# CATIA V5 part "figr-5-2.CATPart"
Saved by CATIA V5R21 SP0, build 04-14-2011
Part number: Part1
Bounding box of the stored display mesh (mm): x -23 to 23, y -104 to 104, z 0 to 68
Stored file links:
  D:\CATIA V5R21 E-RESOURCES\CATIA-V5R21\catia-v5r21-prt\c05-catia-v5r20-prt\catia-v5r21-figr-5-2.CATPart
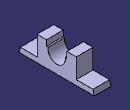
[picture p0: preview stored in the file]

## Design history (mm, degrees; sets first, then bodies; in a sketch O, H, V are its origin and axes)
Sketch1 on yz-plane, origin (0, 0, 0), H (0, 1, 0), V (0, 0, 1)
  line L1 (0, 0) -> (104, 0)
  point P1 (104, 0)
  line L2 (104, 0) -> (100, 14)
  point P2 (100, 14)
  line L3 (100, 14) -> (54, 14)
  point P3 (54, 14)
  line L4 (54, 14) -> (54, 68)
  point P4 (54, 68)
  line L5 (54, 68) -> (28, 68)
  point P5 (28, 68)
  line L6 (28, 68) -> (28, 52)
  point P6 (28, 52)
  line L7 (28, 52) -> (23.6643, 52)
  axis line L8 (0, 0) -> (0, 150)
  point P8 (0, 0)
  construction line L9 through (0, 0) direction (-1, 0)
  construction line L10 through (0, 0) direction (0, 1)
  point P13 (-104, 0)
  point P14 (-100, 14)
  point P15 (-54, 14)
  point P16 (-54, 68)
  point P17 (-28, 68)
  point P18 (-28, 52)
  line L11 (0, 0) -> (-104, 0)
  line L12 (-104, 0) -> (-100, 14)
  line L13 (-100, 14) -> (-54, 14)
  line L14 (-54, 14) -> (-54, 68)
  line L15 (-54, 68) -> (-28, 68)
  line L16 (-28, 68) -> (-28, 52)
  line L17 (-28, 52) -> (-23.6643, 52)
  arc A1 centre (0, 48) radius 24 from (-23.6643, 52) to (23.6643, 52) ccw
  point P19 (0, 48)
  point P20 (13.2665, 68)
  distance P1 P13 = 208
  length L2 V = 14
  length L2 H = 4
  distance L4 L14 = 108
  distance L16 L6 = 56
  distance L1 L5 = 68
  length L6 = 16
  distance P19 L7 = 4
  radius A1 = 24
  horizontal: L1 H, L3 H, L5 H, L7 H
  vertical: L4 V, L6 V, L8 V
  symmetry: O P8 L8, H L9 L8, V L10 L8, P1 P13 L8, P2 P14 L8, P3 P15 L8, P4 P16 L8, P5 P17 L8, P6 P18 L8, L1 L11 L8, L2 L12 L8, L3 L13 L8, L4 L14 L8, L5 L15 L8, L6 L16 L8, L7 L17 L8
  coincidence: P19 L8, A1 P20, P20 L5, O P8
Pad1: profile Sketch1, direction (1, 0, 0), length 23, mirrored extent
Body1 (main body)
